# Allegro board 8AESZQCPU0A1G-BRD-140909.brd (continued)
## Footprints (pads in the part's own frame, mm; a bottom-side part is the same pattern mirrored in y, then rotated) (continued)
SODIMM_204R_R
  round 1.6 hole 1.6 unplated: (0,0)
  round 1.092 hole 1.092 unplated: (66.8,0)
  rect 0.356x2.032 smd: 1(1.75,-4.1) 2(2.05,4.1) 3(2.35,-4.1) 4(2.65,4.1) 5(2.95,-4.1) 6(3.25,4.1) 7(3.55,-4.1) 8(3.85,4.1) 9(4.15,-4.1) 10(4.45,4.1) 11(4.75,-4.1) 12(5.05,4.1) 13(5.35,-4.1) 14(5.65,4.1) 15(5.95,-4.1) 16(6.25,4.1) 17(6.55,-4.1) 18(6.85,4.1) 19(7.15,-4.1) 20(7.45,4.1) 21(7.75,-4.1) 22(8.05,4.1) 23(8.35,-4.1) 24(8.65,4.1) 25(8.95,-4.1) 26(9.25,4.1) 27(9.55,-4.1) 28(9.85,4.1) 29(10.15,-4.1) 30(10.45,4.1) 31(10.75,-4.1) 32(11.05,4.1) 33(11.35,-4.1) 34(11.65,4.1) 35(11.95,-4.1) 36(12.25,4.1) 37(12.55,-4.1) 38(12.85,4.1) 39(13.15,-4.1) 40(13.45,4.1) 41(13.75,-4.1) 42(14.05,4.1) 43(14.35,-4.1) 44(14.65,4.1) 45(14.95,-4.1) 46(15.25,4.1) 47(15.55,-4.1) 48(15.85,4.1) 49(16.15,-4.1) 50(16.45,4.1) 51(16.75,-4.1) 52(17.05,4.1) 53(17.35,-4.1) 54(17.65,4.1) 55(17.95,-4.1) 56(18.25,4.1) 57(18.55,-4.1) 58(18.85,4.1) 59(19.15,-4.1) 60(19.45,4.1) 61(19.75,-4.1) 62(20.05,4.1) 63(20.35,-4.1) 64(20.65,4.1) 65(20.95,-4.1) 66(21.25,4.1) 67(21.55,-4.1) 68(21.85,4.1) 69(22.15,-4.1) 70(22.45,4.1) 71(22.75,-4.1) 72(23.05,4.1) 73(25.75,-4.1) 74(26.05,4.1) 75(26.35,-4.1) 76(26.65,4.1) 77(26.95,-4.1) 78(27.25,4.1) 79(27.55,-4.1) 80(27.85,4.1) 81(28.15,-4.1) 82(28.45,4.1) 83(28.75,-4.1) 84(29.05,4.1) 85(29.35,-4.1) 86(29.65,4.1) 87(29.95,-4.1) 88(30.25,4.1) 89(30.55,-4.1) 90(30.85,4.1) 91(31.15,-4.1) 92(31.45,4.1) 93(31.75,-4.1) 94(32.05,4.1) 95(32.35,-4.1) 96(32.65,4.1) 97(32.95,-4.1) 98(33.25,4.1) 99(33.55,-4.1) 100(33.85,4.1) 101(34.15,-4.1) 102(34.45,4.1) 103(34.75,-4.1) 104(35.05,4.1) 105(35.35,-4.1) 106(35.65,4.1) 107(35.95,-4.1) 108(36.25,4.1) 109(36.55,-4.1) 110(36.85,4.1) 111(37.15,-4.1) 112(37.45,4.1) 113(37.75,-4.1) 114(38.05,4.1) 115(38.35,-4.1) 116(38.65,4.1) 117(38.95,-4.1) 118(39.25,4.1) 119(39.55,-4.1) 120(39.85,4.1) 121(40.15,-4.1) 122(40.45,4.1) 123(40.75,-4.1) 124(41.05,4.1) 125(41.35,-4.1) 126(41.65,4.1) 127(41.95,-4.1) 128(42.25,4.1) 129(42.55,-4.1) 130(42.85,4.1) 131(43.15,-4.1) 132(43.45,4.1) 133(43.75,-4.1) 134(44.05,4.1) 135(44.35,-4.1) 136(44.65,4.1) 137(44.95,-4.1) 138(45.25,4.1) 139(45.55,-4.1) 140(45.85,4.1) 141(46.15,-4.1) 142(46.45,4.1) 143(46.75,-4.1) 144(47.05,4.1) 145(47.35,-4.1) 146(47.65,4.1) 147(47.95,-4.1) 148(48.25,4.1) 149(48.55,-4.1) 150(48.85,4.1) 151(49.15,-4.1) 152(49.45,4.1) 153(49.75,-4.1) 154(50.05,4.1) 155(50.35,-4.1) 156(50.65,4.1) 157(50.95,-4.1) 158(51.25,4.1) 159(51.55,-4.1) 160(51.85,4.1) 161(52.15,-4.1) 162(52.45,4.1) 163(52.75,-4.1) 164(53.05,4.1) 165(53.35,-4.1) 166(53.65,4.1) 167(53.95,-4.1) 168(54.25,4.1) 169(54.55,-4.1) 170(54.85,4.1) 171(55.15,-4.1) 172(55.45,4.1) 173(55.75,-4.1) 174(56.05,4.1) 175(56.35,-4.1) 176(56.65,4.1) 177(56.95,-4.1) 178(57.25,4.1) 179(57.55,-4.1) 180(57.85,4.1) 181(58.15,-4.1) 182(58.45,4.1) 183(58.75,-4.1) 184(59.05,4.1) 185(59.35,-4.1) 186(59.65,4.1) 187(59.95,-4.1) 188(60.25,4.1) 189(60.55,-4.1) 190(60.85,4.1) 191(61.15,-4.1) 192(61.45,4.1) 193(61.75,-4.1) 194(62.05,4.1) 195(62.35,-4.1) 196(62.65,4.1) 197(62.95,-4.1) 198(63.25,4.1) 199(63.55,-4.1) 200(63.85,4.1) 201(64.15,-4.1) 202(64.45,4.1) 203(64.75,-4.1) 204(65.05,4.1)
  rect 3.556x4.699 smd: 205(0.6,-12) 206(66.2,-12)
SOP8_0P65_4P9
  rect 0.508x1.27 smd: 1(-1.102,-2.324) 4(1.102,-2.324) 5(1.102,2.324) 8(-1.102,2.324)
  rect 0.356x1.27 smd: 2(-0.325,-2.324) 3(0.325,-2.324) 6(0.325,2.324) 7(-0.325,2.324)
SOP8_0P65_6P4
  rect 0.61x1.397 smd: 1(-1.102,-3.01) 4(1.102,-3.01) 5(1.102,3.01) 8(-1.102,3.01)
  rect 0.356x1.397 smd: 2(-0.325,-3.01) 3(0.325,-3.01) 6(0.325,3.01) 7(-0.325,3.01)
SOP8_1P27_6
  rect 0.914x1.397 smd: 1(-2.032,-2.857) 4(2.032,-2.857) 5(2.032,2.857) 8(-2.032,2.857)
  rect 0.66x1.397 smd: 2(-0.635,-2.857) 3(0.635,-2.857) 6(0.635,2.857) 7(-0.635,2.857)
SOP8_1P27_7P9
  rect 0.914x1.397 smd: 1(-2.032,-3.81) 4(2.032,-3.81) 5(2.032,3.81) 8(-2.032,3.81)
  rect 0.66x1.397 smd: 2(-0.635,-3.81) 3(0.635,-3.81) 6(0.635,3.81) 7(-0.635,3.81)
SOP14_0P65_6P4_EP
  rect 0.61x1.397 smd: 1(-2.077,-3.01) 7(2.077,-3.01) 8(2.077,3.01) 14(-2.077,3.01)
  rect 0.356x1.397 smd: 2(-1.3,-3.01) 3(-0.65,-3.01) 4(0,-3.01) 5(0.65,-3.01) 6(1.3,-3.01) 9(1.3,3.01) 10(0.65,3.01) 11(0,3.01) 12(-0.65,3.01) 13(-1.3,3.01)
  rect 2.311x2.464 smd: 15(0,0)
SOP14_0P65_6P4_EP_JNPR_1
  rect 0.61x1.397 smd: 1(-2.077,-3.01) 7(2.077,-3.01) 8(2.077,3.01) 14(-2.077,3.01)
  rect 0.356x1.397 smd: 2(-1.3,-3.01) 3(-0.65,-3.01) 4(0,-3.01) 5(0.65,-3.01) 6(1.3,-3.01) 9(1.3,3.01) 10(0.65,3.01) 11(0,3.01) 12(-0.65,3.01) 13(-1.3,3.01)
  rect 2.311x2.464 smd: 15(0,0)
SOT_23
  rect 0.889x1.219 smd: 1(-0.95,-1.219) 2(0.95,-1.219) 3(0,1.219)
SOT_25
  rect 0.61x1.27 smd: 1(-0.965,-1.27) 2(0,-1.27) 3(0.965,-1.27) 4(0.965,1.27) 5(-0.965,1.27)
SOT_363
  rect 0.508x0.889 smd: 1(-0.724,-1.016) 3(0.724,-1.016) 4(0.724,1.016) 6(-0.724,1.016)
  rect 0.356x0.889 smd: 2(0,-1.016) 5(0,1.016)
T30
  round 0.762 smd: 1(0,0)
TO_252AA
  rect 1.27x2.794 smd: 1(-2.286,-4.572) 3(2.286,-4.572)
  rect 5.588x7.62 smd: 2(0,1.778)
unnamed#2
  round 3.2 hole 3.2 unplated: (0,0)
XTAL2_TXC_9H
  rect 1.524x1.778 smd: 1(-1.778,0) 2(1.778,0)
XTAL4_FL2000006
  rect 1.524x1.346 smd: 1(-1.219,-0.978) 2(1.219,-0.978) 3(1.219,0.978) 4(-1.219,0.978)

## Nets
3.3V_FB: C389.1 R77.2 R268.2 U17.1(VFB)
5V_EN: R336.1 U29.7(EN)
5V_FB: C484.1 R339.1 R344.1 U29.2(VFB)
5V_GOOD: R127.2 U29.6(PG)
5V_SS: C483.1 U29.4(SS) U41.3(DRAIN)
12V_HOLD: C135.1 D11.2(CATHODE) R114.1 R336.2 R338.1 U29.13(VIN) U29.14(VCC)
AGND_V1P0: C158.2 N56.2 N57.1 R128.1 U31.4(AGND) U31.17(GND)
GND: A1.3 A1.4 A1.6 A1.7 A1.8 C1.2 C2.2 C3.2 C4.2 C5.2 C7.2 C8.2 C9.2 C10.2 C11.2 C12.2 C13.2 C14.2 C15.2 C17.2 C18.2 C19.2 C21.2 C22.2 C24.2 C25.2 C26.2 C27.2 C28.2 C30.2 C39.2 C42.2 C43.2 C44.2 C45.2 C46.2 C47.2 C48.2 C49.2 C50.2 C51.2 C52.2 C53.2 C54.2 C55.2 C56.2 C57.2 C58.2 C59.2 C60.2 C61.2 C62.2 C63.1 C64.2 C65.2 C66.1 C68.2 C69.2 C70.2 C71.2 C72.2 C76.2 C77.2 C78.2 C80.2 C81.2 C82.2 C83.2 C84.2 C86.1 C88.2 C89.2 C90.2 C91.2 C92.2 C93.2 C94.2 C95.2 C96.1 C97.2 C98.2 C99.2 C100.2 C101.2 C102.2 C105.2 C108.1 C114.2 C115.2 C116.2 C117.2 C118.2 C119.2 C120.2 C121.2 C122.2 C123.2 C124.1 C125.2 C126.1 C127.2 C128.2 C129.2 C130.1 C131.2 C132.2 C133.2 C134.2 C135.2 C136.1 C137.2 C138.2 C139.2 C140.2 C141.2 C142.2 C143.2 C144.2 C145.2 C146.2 C147.2 C148.1 C149.2 C151.2 C152.2 C153.1 C154.1 C155.1 C156.2 C157.2 C159.2 C160.2 C161.2 C162.2 C163.2 C165.2 C166.2 C167.2 C168.2 C169.2 C170.2 C171.2 C172.2 C173.2 C174.2 C175.2 C176.2 C177.2 C178.2 C179.2 C180.2 C181.2 C182.2 C183.2 C185.2 C186.2 C187.2 C188.2 C189.2 C190.2 C191.2 C192.2 C193.2 C194.2 C195.2 C196.2 C197.2 C198.2 C199.2 C200.2 C201.2 C202.2 C203.2 C204.2 C205.2 C206.2 C207.2 C208.2 C209.2 C210.2 C211.2 C212.2 C213.2 C214.2 C215.2 C216.2 C217.2 C218.2 C219.2 C221.2 C222.2 C223.2 C224.2 C225.2 C226.2 C227.2 C228.2 C229.2 C230.2 C231.2 C232.2 C233.2 C234.2 C236.2 C237.2 C238.2 C241.2 C244.2 C245.2 C247.2 C248.2 C249.2 C250.2 C251.2 C252.2 C255.2 C256.2 C257.2 C258.2 C259.2 C260.2 C261.2 C262.2 C263.2 C264.2 C265.2 C266.2 C267.2 C268.2 C269.2 C270.2 C271.2 C272.2 C273.2 C274.2 C275.2 C276.2 C277.2 C278.2 C279.2 C280.2 C281.2 C282.2 C283.2 C284.2 C285.2 C286.2 C287.2 C288.2 C289.2 C290.2 C291.2 C293.2 C294.2 C295.2 C296.2 C299.2 C300.2 C301.2 C302.2 C303.2 C304.2 C305.2 C306.2 C307.2 C308.2 C309.2 C310.2 C311.2 C312.2 C315.2 C316.2 C317.2 C318.2 C319.2 C320.2 C321.2 C322.2 C323.2 C324.2 C325.2 C326.2 C327.1 C328.2 C329.2 C330.2 C331.2 C332.2 C333.2 C334.2 C335.2 C336.2 C337.2 C339.2 C340.2 C341.2 C342.2 C343.2 C344.2 C345.2 C346.2 C347.2 C349.2 C350.2 C351.2 C352.2 C353.2 C354.2 C355.2 C356.2 C357.2 C358.2 C359.2 C360.2 C361.2 C362.2 C363.2 C365.2 C366.2 C367.2 C368.2 C369.2 C370.2 C371.2 C372.2 C373.2 C374.2 C375.2 C376.2 C377.2 C378.2 C379.2 C380.2 C381.2 C382.2 C383.2 C384.2 C385.2 C386.2 C387.2 C388.2 C390.2 C391.2 C392.2 C393.2 C394.2 C396.2 C397.2 C398.2 C399.2 C400.2 C401.2 C402.2 C403.2 C404.2 C405.2 C406.2 C407.2 C408.2 C409.2 C410.2 C411.2 C412.2 C413.2 C415.2 C416.2 C417.2 C418.2 C420.2 C422.2 C423.2 C424.2 C425.2 C426.2 C427.2 C432.2 C434.2 C435.2 C436.2 C437.2 C438.2 C439.2 C440.2 C441.2 C442.2 C443.2 C445.2 C446.2 C449.2 C451.2 C453.2 C454.2 C455.2 C456.1 C457.2 C458.2 C459.2 C460.2 C461.2 C462.1 C463.2 C464.2 C465.2 C466.2 C467.2 C468.2 C469.2 C470.2 C471.2 C472.2 C473.2 C474.2 C475.2 C476.2 C477.2 C479.2 C480.2 C481.2 C482.2 C483.2 C485.2 C489.1 C490.1 C491.1 C492.1 C493.1 C494.1 C495.1 C496.1 C498.2 C499.2 C500.2 C501.2 J1.3 J2.3 J3.3 J4.3 J5.3 JP2.4 JP3.2 JP3.10 JP4.1 JP4.2 JP4.3 JP4.4 JP5.4 N3.2 N13.2 N18.2 N29.2 N31.1 N32.1 N36.1 N39.2 N41.2 N45.2 N51.1 N56.1 N58.2 P1.2(GND24) P1.3(GND1) P1.8(GND25) P1.9(GND2) P1.11(DM0) P1.14(GND26) P1.17(GND3) P1.20(GND27) P1.23(GND4) P1.26(GND28) P1.28(DM1) P1.29(GND5) P1.32(GND29) P1.35(GND6) P1.38(GND30) P1.41(GND7) P1.44(DM2) P1.46(GND31) P1.47(GND8) P1.52(GND32) P1.53(GND9) P1.58(GND33) P1.59(DM3) P1.61(GND10) P1.64(GND34) P1.67(GND11) P1.70(GND35) P1.73(GND12) P1.76(DM8) P1.78(GND36) P1.79(GND13) P1.137(GND14) P1.138(GND37) P1.140(DM4) P1.143(GND15) P1.146(GND38) P1.149(GND16) P1.152(GND39) P1.155(GND17) P1.157(DM5) P1.158(GND40) P1.163(GND18) P1.164(GND41) P1.169(GND19) P1.170(GND42) P1.172(DM6) P1.175(GND20) P1.178(GND43) P1.181(GND21) P1.184(GND44#184) P1.187(GND22) P1.189(DM7) P1.190(GND44#190) P1.195(GND23) P1.196(GND45) P1.205(GATE1) P1.206(GATE2) P2.1(GND0) P2.2(GND1) P2.7(GND2) P2.8(GND3) P2.13(GND4) P2.14(GND5) P2.19(GND6) P2.20(GND7) P2.25(GND8) P2.26(GND9) P2.31(GND10) P2.32(GND11) P2.37(GND12) P2.38(GND13) P2.49(GND14) P2.50(GND15) P2.59(GND16) P2.60(GND17) P3.1 P3.4 P3.7 P3.11 P3.12 P3.13 P3.17 P3.19 P3.23 P3.24 P4.2(GND24) P4.3(GND1) P4.8(GND25) P4.9(GND2) P4.11(DM0) P4.14(GND26) P4.17(GND3) P4.20(GND27) P4.23(GND4) P4.26(GND28) P4.28(DM1) P4.29(GND5) P4.32(GND29) P4.35(GND6) P4.38(GND30) P4.41(GND7) P4.44(DM2) P4.46(GND31) P4.47(GND8) P4.52(GND32) P4.53(GND9) P4.58(GND33) P4.59(DM3) P4.61(GND10) P4.64(GND34) P4.67(GND11) P4.70(GND35) P4.73(GND12) P4.76(DM8) P4.78(GND36) P4.79(GND13) P4.137(GND14) P4.138(GND37) P4.140(DM4) P4.143(GND15) P4.146(GND38) P4.149(GND16) P4.152(GND39) P4.155(GND17) P4.157(DM5) P4.158(GND40) P4.163(GND18) P4.164(GND41) P4.169(GND19) P4.170(GND42) P4.172(DM6) P4.175(GND20) P4.178(GND43) P4.181(GND21) P4.184(GND44#184) P4.187(GND22) P4.189(DM7) P4.190(GND44#190) P4.195(GND23) P4.196(GND45) P4.205(GATE1) P4.206(GATE2) R1.2 R3.2 R10.2 R11.1 R14.1 R25.1 R35.2 R39.2 R55.1 R64.2 R71.2 R76.2 R77.1 R85.1 R86.1 R99.2 R106.2 R116.2 R119.2 R121.2 R123.1 R124.2 R126.1 R129.2 R130.2 R135.2 R137.2 R144.1 R149.2 R155.1 R157.1 R164.2 R165.2 R166.2 R167.2 R173.1 R177.2 R178.2 R179.2 R181.2 R183.2 R188.2 R189.2 R192.2 R197.2 R211.2 R212.2 R213.2 R221.2 R223.2 R224.2 R226.2 R227.2 R228.2 R231.2 R234.2 R237.1 R238.2 R242.1 R245.1 R255.1 R261.2 R262.2 R263.2 R264.1 R265.2 R271.1 R274.2 R275.2 R277.2 R278.1 R279.1 R280.1 R286.2 R294.1 R295.1 R299.2 R303.2 R304.1 R305.1 R306.2 R317.2 R318.2 R321.2 R322.2 R325.1 R332.1 R333.2 R341.2 R344.2 R345.2 R346.1 S1.A1(PRSNT#) S1.A4(GND#A4) S1.A12(GND#A12) S1.A15(GND#A15) S1.A16(GND#A16) S1.A19(GND#A19) S1.A20(GND#A20) S1.A23(GND#A23) S1.A24(GND#A24) S1.A27(GND#A27) S1.A28(GND#A28) S1.A31(GND#A31) S1.A32(GND#A32) S1.A35(GND#A35) S1.A36(GND#A36) S1.A39(GND#A39) S1.A40(GND#A40) S1.A43(GND#A43) S1.A44(GND#A44) S1.A47(GND#A47) S1.A48(GND#A48) S1.A51(GND#A51) S1.A52(GND#A52) S1.A55(GND#A55) S1.A56(GND#A56) S1.A59(GND#A59) S1.A60(GND#A60) S1.A63(GND#A63) S1.A64(GND#A64) S1.A67(GND#A67) S1.A68(GND#A68) S1.A71(GND#A71) S1.A72(GND#A72) S1.A75(GND#A75) S1.A76(GND#A76) S1.A79(GND#A79) S1.A80(GND#A80) S1.B4(GND#B4) S1.B7(GND#B7) S1.B13(GND#B13) S1.B14(GND#B14) S1.B17(GND#B17) S1.B18(GND#B18) S1.B21(GND#B21) S1.B22(GND#B22) S1.B25(GND#B25) S1.B26(GND#B26) S1.B29(GND#B29) S1.B30(GND#B30) S1.B33(GND#B33) S1.B34(GND#B34) S1.B37(GND#B37) S1.B38(GND#B38) S1.B41(GND#B41) S1.B42(GND#B42) S1.B45(GND#B45) S1.B46(GND#B46) S1.B49(GND#B49) S1.B50(GND#B50) S1.B53(GND#B53) S1.B54(GND#B54) S1.B57(GND#B57) S1.B58(GND#B58) S1.B61(GND#B61) S1.B62(GND#B62) S1.B65(GND#B65) S1.B66(GND#B66) S1.B69(GND#B69) S1.B70(GND#B70) S1.B73(GND#B73) S1.B74(GND#B74) S1.B77(GND#B77) S1.B78(GND#B78) S1.B81(GND#B81) S1.B82(GND#B82) U1.3(GND) U2.1(CSIN_N) U2.2(CSIN_P) U2.4(PGND1) U2.12(PGND2) U2.13(PGND3) U2.21(LGND) U2.22(REFIN) U3.26(VRTN_L2) U3.27(VSEN_L2) U3.41(GND) U5.4(GND) U6.2(GND) U7.A1(GNDIO#A1) U7.A16(GNDIO#A16) U7.B2(GNDIO#B2) U7.B15(GNDIO#B15) U7.F7(IO_2_F7/DIFFIO_T8P) U7.G5(GNDIO#G5) U7.G6(IO_1_G6) U7.G7(GNDIO#G7) U7.G8(GNDIO#G8) U7.G9(GNDIO#G9) U7.G10(GNDIO#G10) U7.H7(GNDINT#H7) U7.H9(GNDINT#H9) U7.J8(GNDINT#J8) U7.J10(GNDINT#J10) U7.K7(GNDIO#K7) U7.K8(GNDIO#K8) U7.K9(GNDIO#K9) U7.K10(GNDIO#K10) U7.K11(IO_3_K11) U7.L10(IO_4_L10) U7.R2(GNDIO#R2) U7.R15(GNDIO#R15) U7.T1(GNDIO#T1) U7.T6(IO_4_T6/DIFFIO_B9P) U7.T16(GNDIO#T16) U8.4(GND) U9.4(GND) U10.2(GND) U11.3(GND) U12.1(CSIN_N) U12.2(CSIN_P) U12.4(PGND1) U12.12(PGND2) U12.13(PGND3) U12.21(LGND) U12.22(REFIN) U13.3(GND) U14.A5(VSS#A5) U14.A9(VSS#A9) U14.A12(VSS#A12) U14.A15(VSS#A15) U14.A18(VSS#A18) U14.A24(VSS#A24) U14.A30(VSS#A30) U14.A33(VSS#A33) U14.A45(VSS#A45) U14.A48(VSS#A48) U14.A51(VSS#A51) U14.A57(VSS#A57) U14.A59(VSS#A59) U14.A61(VSS#A61) U14.A62(VSS#A62) U14.A64(VSS#A64) U14.A66(VSS#A66) U14.AA3(VSS#AA3) U14.AA5(VSS#AA5) U14.AA23(VSS#AA23) U14.AA25(VSS#AA25) U14.AA26(VSS#AA26) U14.AA28(VSS#AA28) U14.AA29(VSS#AA29) U14.AA31(VSS#AA31) U14.AA36(VSS#AA36) U14.AA42(VSS#AA42) U14.AA44(VSS#AA44) U14.AA62(VSS#AA62) U14.AA64(VSS#AA64) U14.AA66(VSS#AA66) U14.AB1(VSS#AB1) U14.AB5(VSS#AB5) U14.AB20(VSS#AB20) U14.AC12(VSS#AC12) U14.AC18(VSS#AC18) U14.AC20(VSS#AC20) U14.AC21(VSS#AC21) U14.AC23(VSS#AC23) U14.AC28(VSS#AC28) U14.AC29(VSS#AC29) U14.AC31(VSS#AC31) U14.AC32(VSS#AC32) U14.AC34(VSS#AC34) U14.AC36(VSS#AC36) U14.AC46(VSS#AC46) U14.AC50(VSS#AC50) U14.AC55(VSS#AC55) U14.AC59(VSS#AC59) U14.AD2(VSS#AD2) U14.AD4(VSS#AD4) U14.AD5(VSS#AD5) U14.AD9(VSS#AD9) U14.AD14(VSS#AD14) U14.AD17(VSS#AD17) U14.AD18(VSS#AD18) U14.AD20(VSS#AD20) U14.AD34(VSS#AD34) U14.AD41(VSS#AD41) U14.AD46(VSS#AD46) U14.AD47(VSS#AD47) U14.AD52(VSS#AD52) U14.AD56(VSS#AD56) U14.AD62(VSS#AD62) U14.AE47(VSS#AE47) U14.AE64(VSS#AE64) U14.AF28(VSS#AF28) U14.AF44(VSS#AF44) U14.AF62(VSS#AF62) U14.AG5(VSS#AG5) U14.AG10(VSS#AG10) U14.AG16(VSS#AG16) U14.AG23(VSS#AG23) U14.AG25(VSS#AG25) U14.AG26(VSS#AG26) U14.AG28(VSS#AG28) U14.AG34(VSS#AG34) U14.AG41(VSS#AG41) U14.AG44(VSS#AG44) U14.AG48(VSS#AG48) U14.AG53(VSS#AG53) U14.AG57(VSS#AG57) U14.AG63(VSS#AG63) U14.AG64(VSS#AG64) U14.AG66(VSS#AG66) U14.AH11(VSS#AH11) U14.AH17(VSS#AH17) U14.AH53(VSS#AH53) U14.AH57(VSS#AH57) U14.AH62(VSS#AH62) U14.AJ28(VSS#AJ28) U14.AJ32(VSS#AJ32) U14.AJ44(VSS#AJ44) U14.AJ46(VSS#AJ46) U14.AJ47(VSS#AJ47) U14.AK3(VSS#AK3) U14.AK5(VSS#AK5) U14.AK62(VSS#AK62) U14.AK64(VSS#AK64) U14.AK66(VSS#AK66) U14.AL1(VSS#AL1) U14.AL5(VSS#AL5) U14.AL9(VSS#AL9) U14.AL14(VSS#AL14) U14.AL17(VSS#AL17) U14.AL18(VSS#AL18) U14.AL20(VSS#AL20) U14.AL29(VSS#AL29) U14.AL38(VSS#AL38) U14.AL42(VSS#AL42) U14.AL44(VSS#AL44) U14.AL50(VSS#AL50) U14.AL55(VSS#AL55) U14.AL59(VSS#AL59) U14.AM12(VSS#AM12) U14.AM18(VSS#AM18) U14.AM20(VSS#AM20) U14.AM21(VSS#AM21) U14.AM23(VSS#AM23) U14.AM44(VSS#AM44) U14.AM46(VSS#AM46) U14.AM50(VSS#AM50) U14.AM55(VSS#AM55) U14.AM59(VSS#AM59) U14.AN5(VSS#AN5) U14.AN47(VSS#AN47) U14.AN66(VSS#AN66) U14.AP5(VSS#AP5) U14.AP23(VSS#AP23) U14.AP25(VSS#AP25) U14.AP26(VSS#AP26) U14.AP28(VSS#AP28) U14.AP29(VSS#AP29) U14.AP31(VSS#AP31) U14.AP32(VSS#AP32) U14.AP34(VSS#AP34) U14.AP36(VSS#AP36) U14.AP38(VSS#AP38) U14.AP39(VSS#AP39) U14.AP41(VSS#AP41) U14.AP42(VSS#AP42) U14.AP44(VSS#AP44) U14.AP46(VSS#AP46) U14.AP64(VSS#AP64) U14.AR8(VSS#AR8) U14.AR13(VSS#AR13) U14.AR17(VSS#AR17) U14.AR19(VSS#AR19) U14.AR50(VSS#AR50) U14.AR56(VSS#AR56) U14.AR60(VSS#AR60) U14.AR62(VSS#AR62) U14.AT5(VSS#AT5) U14.AT11(VSS#AT11) U14.AT16(VSS#AT16) U14.AT17(VSS#AT17) U14.AT19(VSS#AT19) U14.AT44(VSS#AT44) U14.AT53(VSS#AT53) U14.AT57(VSS#AT57) U14.AT64(VSS#AT64) U14.AT66(VSS#AT66) U14.AU4(VSS#AU4) U14.AU44(VSSA_USB#AU44) U14.AU62(VSS#AU62) U14.AV2(VSS#AV2) U14.AV4(VSS#AV4) U14.AV5(VSS#AV5) U14.AW5(VSS#AW5) U14.AW9(VSS#AW9) U14.AW14(VSS#AW14) U14.AW19(VSS#AW19) U14.AW23(VSS#AW23) U14.AW25(VSS#AW25) U14.AW26(VSS#AW26) U14.AW28(VSS#AW28) U14.AW30(VSS#AW30) U14.AW31(VSS#AW31) U14.AW32(VSS#AW32) U14.AW34(VSS#AW34) U14.AW44(VSSA_USB#AW44) U14.AW46(VSS#AW46) U14.AW47(VSS#AW47) U14.AW49(VSS#AW49) U14.AW50(VSS#AW50) U14.AW52(VSS#AW52) U14.AW55(VSS#AW55) U14.AW59(VSS#AW59) U14.AY5(VSS#AY5) U14.AY12(VSS#AY12) U14.AY38(VSS#AY38) U14.AY45(VSS#AY45) U14.AY52(VSS#AY52) U14.AY55(VSS#AY55) U14.AY62(VSS#AY62) U14.B10(VSS#B10) U14.B26(VSS#B26) U14.B41(VSS#B41) U14.B55(VSS#B55) U14.BA17(VSS#BA17) U14.BA29(VSS#BA29) U14.BA34(VSS#BA34) U14.BA42(VSS#BA42) U14.BA49(VSS#BA49) U14.BB5(VSS#BB5) U14.BB17(VSS#BB17) U14.BB34(VSS#BB34) U14.BB53(VSS#BB53) U14.BB54(VSS#BB54) U14.BB56(VSS#BB56) U14.BB57(VSS#BB57) U14.BB62(VSS#BB62) U14.BB65(VSS#BB65) U14.BB66(VSS#BB66) U14.BC5(VSS#BC5) U14.BC30(VSS#BC30) U14.BC37(VSS#BC37) U14.BC46(VSS#BC46) U14.BD32(VSS#BD32) U14.BD34(VSS#BD34) U14.BD38(VSS#BD38) U14.BD41(VSS#BD41) U14.BD45(VSS#BD45) U14.BD50(VSS#BD50) U14.BD53(VSS#BD53) U14.BD59(VSS#BD59) U14.BD60(VSS#BD60) U14.BD62(VSS#BD62) U14.BD63(VSS#BD63) U14.BD65(VSS#BD65) U14.BE5(VSS#BE5) U14.BE32(VSS#BE32) U14.BE42(VSS#BE42) U14.BE49(VSS#BE49) U14.BE57(VSS#BE57) U14.BE66(VSS#BE66) U14.BF1(VSS#BF1) U14.BF3(VSS#BF3) U14.BF4(VSS#BF4) U14.BF29(VSS#BF29) U14.BF62(VSS#BF62) U14.BG1(VSS#BG1) U14.BG32(VSS#BG32) U14.BG37(VSS#BG37) U14.BG46(VSS#BG46) U14.BG54(VSS#BG54) U14.BG63(VSS#BG63) U14.BG66(VSS#BG66) U14.BH32(VSS#BH32) U14.BH34(VSS#BH34) U14.BH41(VSS#BH41) U14.BH50(VSS#BH50) U14.BH60(VSS#BH60) U14.BH62(VSS#BH62) U14.BJ1(VSS#BJ1) U14.BJ66(VSS#BJ66) U14.BK1(VSS#BK1) U14.BK8(VSS#BK8) U14.BK10(VSS#BK10) U14.BK15(VSS#BK15) U14.BK17(VSS#BK17) U14.BK18(VSS#BK18) U14.BK19(VSS#BK19) U14.BK21(VSS#BK21) U14.BK22(VSS#BK22) U14.BK24(VSS#BK24) U14.BK26(VSS#BK26) U14.BK27(VSS#BK27) U14.BK28(VSS#BK28) U14.BK30(VSS#BK30) U14.BK31(VSS#BK31) U14.BK36(VSS#BK36) U14.BK37(VSS#BK37) U14.BK39(VSS#BK39) U14.BK42(VSS#BK42) U14.BK44(VSS#BK44) U14.BK45(VSS#BK45) U14.BK46(VSS#BK46) U14.BK48(VSS#BK48) U14.BK49(VSS#BK49) U14.BK51(VSS#BK51) U14.BK53(VSS#BK53) U14.BK56(VSS#BK56) U14.BK57(VSS#BK57) U14.BK58(VSS#BK58) U14.BK64(VSS#BK64) U14.BK66(VSS#BK66) U14.BL14(VSS#BL14) U14.BL19(VSS#BL19) U14.BL25(VSS#BL25) U14.BL30(VSS#BL30) U14.BL34(VSS#BL34) U14.BL37(VSS#BL37) U14.BL43(VSS#BL43) U14.BM1(VSS#BM1) U14.BM3(VSS#BM3) U14.BM5(VSS#BM5) U14.BM22(VSS#BM22) U14.BM45(VSS#BM45) U14.BM61(VSS#BM61) U14.BM62(VSS#BM62) U14.BM64(VSS#BM64) U14.BM66(VSS#BM66) U14.BN14(VSS#BN14) U14.BN30(VSS#BN30) U14.BN37(VSS#BN37) U14.BP1(VSS#BP1) U14.BP3(VSS#BP3) U14.BP5(VSS#BP5) U14.BP10(VSS#BP10) U14.BP13(VSS#BP13) U14.BP22(VSS#BP22) U14.BP31(VSS#BP31) U14.BP37(VSS#BP37) U14.BP40(VSS#BP40) U14.BP46(VSS#BP46) U14.BP52(VSS#BP52) U14.BP55(VSS#BP55) U14.BP58(VSS#BP58) U14.BP59(VSS#BP59) U14.BP61(VSS#BP61) U14.BP62(VSS#BP62) U14.BP64(VSS#BP64) U14.BP66(VSS#BP66) U14.C3(VSS#C3) U14.C6(VSS#C6) U14.C18(VSS#C18) U14.C33(VSS#C33) U14.C45(VSS#C45) U14.C49(VSS#C49) U14.C51(VSS#C51) U14.C58(VSS#C58) U14.C64(VSS#C64) U14.C66(VSS#C66) U14.D6(VSS#D6) U14.D10(VSS#D10) U14.D26(VSS#D26) U14.D33(VSS#D33) U14.D41(VSS#D41) U14.D42(VSS#D42) U14.D51(VSS#D51) U14.D55(VSS#D55) U14.D59(VSS#D59) U14.E1(VSS#E1) U14.E3(VSS#E3) U14.E10(VSS#E10) U14.E13(VSS#E13) U14.E14(VSS#E14) U14.E16(VSS#E16) U14.E18(VSS#E18) U14.E19(VSS#E19) U14.E21(VSS#E21) U14.E22(VSS#E22) U14.E23(VSS#E23) U14.E25(VSS#E25) U14.E27(VSS#E27) U14.E28(VSS#E28) U14.E30(VSS#E30) U14.E31(VSS#E31) U14.E34(VSS#E34) U14.E36(VSS#E36) U14.E37(VSS#E37) U14.E39(VSS#E39) U14.E40(VSS#E40) U14.E41(VSS#E41) U14.E43(VSS#E43) U14.E45(VSS#E45) U14.E46(VSS#E46) U14.E48(VSS#E48) U14.E49(VSS#E49) U14.E50(VSS#E50) U14.E52(VSS#E52) U14.E54(VSS#E54) U14.E55(VSS#E55) U14.E59(VSS#E59) U14.E61(VSS#E61) U14.E64(VSS#E64) U14.E66(VSS#E66) U14.F1(VSS#F1) U14.F4(VSS#F4) U14.F5(VSS#F5) U14.F63(VSS#F63) U14.F66(VSS#F66) U14.G32(VSS#G32) U14.G34(VSS#G34) U14.G41(VSS#G41) U14.G48(VSS#G48) U14.G56(VSS#G56) U14.G59(VSS#G59) U14.H1(VSS#H1) U14.H34(VSS#H34) U14.H37(VSS#H37) U14.H38(VSS#H38) U14.H41(VSS#H41) U14.H44(VSS#H44) U14.H46(VSS#H46) U14.H52(VSS#H52) U14.H54(VSS#H54) U14.H56(VSS#H56) U14.H58(VSS#H58) U14.H59(VSS#H59) U14.H66(VSS#H66) U14.J29(VSS#J29) U14.J63(VSS#J63) U14.J64(VSS#J64) U14.J66(VSS#J66) U14.K1(VSS#K1) U14.K32(VSS#K32) U14.K34(VSS#K34) U14.K42(VSS#K42) U14.K50(VSS#K50) U14.K62(VSS#K62) U14.L30(VSS#L30) U14.L34(VSS#L34) U14.L48(VSS#L48) U14.L50(VSS#L50) U14.L60(VSS#L60) U14.M5(VSS#M5) U14.M37(VSS#M37) U14.M38(VSS#M38) U14.M44(VSS#M44) U14.M46(VSS#M46) U14.M52(VSS#M52) U14.M54(VSS#M54) U14.M56(VSS#M56) U14.M57(VSS#M57) U14.M59(VSS#M59) U14.M60(VSS#M60) U14.M66(VSS#M66) U14.N1(VSS#N1) U14.N5(VSS#N5) U14.N10(VSS#N10) U14.N34(VSS#N34) U14.N48(VSS#N48) U14.N50(VSS#N50) U14.N62(VSS#N62) U14.N63(VSS#N63) U14.N65(VSS#N65) U14.P29(VSS#P29) U14.P32(VSS#P32) U14.P34(VSS#P34) U14.P37(VSS#P37) U14.P44(VSS#P44) U14.R2(VSS#R2) U14.R4(VSS#R4) U14.R5(VSS#R5) U14.R12(VSS#R12) U14.R30(VSS#R30) U14.R38(VSS#R38) U14.R52(VSS#R52) U14.R56(VSS#R56) U14.R62(VSS#R62) U14.T5(VSS#T5) U14.T18(VSS#T18) U14.T20(VSS#T20) U14.T21(VSS#T21) U14.T23(VSS#T23) U14.T28(VSS#T28) U14.T29(VSS#T29) U14.T31(VSS#T31) U14.T34(VSS#T34) U14.T36(VSS#T36) U14.T41(VSS#T41) U14.T42(VSS#T42) U14.T47(VSS#T47) U14.T52(VSS#T52) U14.T56(VSS#T56) U14.T62(VSS#T62) U14.U9(VSS#U9) U14.U14(VSS#U14) U14.U62(VSS#U62) U14.U63(VSS#U63) U14.U65(VSS#U65) U14.V5(VSS#V5) U14.V32(VSS#V32) U14.V36(VSS#V36) U14.V42(VSS#V42) U14.V44(VSS#V44) U14.W4(VSS#W4) U14.W11(VSS#W11) U14.W16(VSS#W16) U14.W17(VSS#W17) U14.W19(VSS#W19) U14.W32(VSS#W32) U14.W36(VSS#W36) U14.W39(VSS#W39) U14.W42(VSS#W42) U14.W48(VSS#W48) U14.W53(VSS#W53) U14.W57(VSS#W57) U14.W62(VSS#W62) U14.Y5(VSS#Y5) U14.Y8(VSS#Y8) U14.Y13(VSS#Y13) U14.Y17(VSS#Y17) U14.Y19(VSS#Y19) U14.Y48(VSS#Y48) U14.Y51(VSS#Y51) U14.Y56(VSS#Y56) U14.Y60(VSS#Y60) U15.4(GND) U16.4(GND) U17.23(PWPD) U19.4(S) U19.8(S1) U20.7(GND) U20.11(GND_PAD) U21.4(GND) U21.41(EPAD) U23.41(GND) U24.4(VSS) U25.5(GND) U25.8(PGND1) U25.9(PGND2) U25.15(PWPD) U26.6(GND1) U26.11(GND2) U27.11(GNDPCI) U27.12(GND25) U27.17(GND48) U27.24(GNDSATA) U27.25(GNDSRC1) U27.34(GNDSRC2) U27.44(GNDDIF) U27.48(GNDREF) U27.49(TPAD) U28.6(GND1) U28.11(GND2) U29.5(GND) U29.8(PGND1) U29.9(PGND2) U29.15(PWPD) U30.6(GND1) U30.11(GND2) U31.11(PGND) U32.2(GND) U33.2(VSS) U34.2(GND) U35.2(VSS) U36.3(GND) U37.3(GND) U38.4(PGND) U38.8(GND) U38.11(GND_PAD) U39.2(SOURCE) U41.2(SOURCE) U42.2(SOURCE) X1.2(GND) X3.2(G2) X3.4(G4)
V1P0: C78.1 C159.1 C160.1 C161.1 C239.2 C257.1 C260.1 C284.1 C286.1 C287.1 C288.1 C290.1 C294.1 C303.1 C304.1 C305.1 C306.1 C316.1 C318.1 C330.1 C342.1 C343.1 C349.1 C350.1 C352.1 C354.1 C357.1 C359.1 C363.1 C373.1 C375.1 C376.1 C377.1 C381.1 C393.1 C397.1 C410.1 C411.1 C412.1 C498.1 C499.1 C500.1 C501.1 L3.1 L12.2 L14.2 L16.2 L17.1 N6.2 N59.2 N60.1 P2.43(VCC_OBS_AB) P2.44(VCC_OBS_CD) R23.1 R45.2 R50.2 R51.1 R66.2 R69.2 R75.2 R174.1 R184.2 R185.2 R198.2 R202.1 R220.2 R225.1 R236.2 U6.6(VREFB) U10.6(VREFB) U14.AA21(VCCADDR_1_1P0#AA21) U14.AA38(VCCDIGXXXSUS_1P03#AA38) U14.AA39(VCCDIGXXXSUS_1P03#AA39) U14.AA41(VCCDIGXXXSUS_1P03#AA41) U14.AC38(VCCDIGXXXSUS_1P03#AC38) U14.AC39(VCCDIGXXXSUS_1P03#AC39) U14.AC41(VCCDIGXXXSUS_1P03#AC41) U14.AC42(VCCFHVSOCSI0_1P03#AC42) U14.AC44(VCCFHVSOCSI0_1P03#AC44) U14.AD28(VCCFHVCPUSI0_MOD0_1P03) U14.AD29(VCCFHVCPUSI0_MOD2_1P03) U14.AD38(VCCDIGXXXSI0_1P03#AD38) U14.AF38(VCCDIGXXXSI0_1P03#AF38) U14.AG38(VCCDIGXXXSI0_1P03#AG38) U14.AJ29(VCCFHVCPUSI0_MOD3_1P03) U14.AJ38(VCCDIGXXXSI0_1P03#AJ38) U14.AL28(VCCFHVCPUSI0_MOD1_1P03) U14.AT21(VCCADDR_0_1P0#AT21) U14.AT23(VCCADDR_0_1P0#AT23) U14.AT25(VCCADDR_0_1P0#AT25) U14.AT26(VCCADDR_0_1P0#AT26) U14.AT28(VCCADDR_0_1P0#AT28) U14.AT36(VCCA_PCIE_1P0#AT36) U14.AT38(VCCA_PCIE_1P0#AT38) U14.AT39(VCCAREF_PCIE_HVGEN) U14.AT41(VCCDUSBSUS_1P0) U14.AT42(VCCAUSB_1P0) U14.AU21(VCCADLLDDR_0_1P0#AU21) U14.AU23(VCCADLLDDR_0_1P0#AU23) U14.AU25(VCCADLLDDR_0_1P0#AU25) U14.AU26(VCCADLLDDR_0_1P0#AU26) U14.AU28(VCCADLLDDR_0_1P0#AU28) U14.AU36(VCCA_PCIE_1P0#AU36) U14.AU38(VCCA_PCIE_1P0#AU38) U14.AU39(VCCA_PCIE_1P0#AU39) U14.AU41(VCCDUSB_1P0#AU41) U14.AW36(VCCA_PCIE_1P0#AW36) U14.AW41(VCCDUSB_1P0#AW41) U14.AY37(VCCAPLL_PCIE_1P0#AY37) U14.BA37(VCCAPLL_PCIE_1P0#BA37) U14.K41(VCCA_SATA_1P0#K41) U14.L41(VCCA_SATA_1P0#L41) U14.L42(VCCA_SATA3_1P0#L42) U14.N41(VCCA_SATA_1P0#N41) U14.N42(VCCA_SATA3_1P0#N42) U14.P41(VCCA_SATA_1P0#P41) U14.P42(VCCA_SATA3_1P0#P42) U14.R44(VCCAPLL_SATA3_1P0#R44) U14.R46(VCCAPLL_SATA_1P0#R46) U14.T37(VCCA_GBE_1P0#T37) U14.T39(VCCAREF_GBE_HVGEN#T39) U14.T44(VCCAPLL_SATA3_1P0#T44) U14.T45(VCCAPLL_SATA_1P0#T45) U14.V20(VCCADLLDDR_1_1P0#V20) U14.V21(VCCADLLDDR_1_1P0#V21) U14.V23(VCCADLLDDR_1_1P0#V23) U14.V25(VCCADLLDDR_1_1P0#V25) U14.V26(VCCADLLDDR_1_1P0#V26) U14.V38(VCCA_GBE_1P0#V38) U14.V39(VCCAREF_GBE_HVGEN#V39) U14.V41(VCCAPLL_GBE_1P0#V41) U14.V46(VCCAREF_SATA_HVGEN#V46) U14.W21(VCCADDR_1_1P0#W21) U14.W23(VCCADDR_1_1P0#W23) U14.W25(VCCADDR_1_1P0#W25) U14.W26(VCCADDR_1_1P0#W26) U14.W38(VCCA_GBE_1P0#W38) U14.W41(VCCAPLL_GBE_1P0#W41) U14.W44(VCCAREF_SATA_HVGEN#W44) U14.W46(VCCAREF_SATA_HVGEN#W46)
V1P0_LDOOUT: C165.1 U31.6(S_CTRL) U31.10(VCC/LDO_OUT)
V1P1: C113.2 C120.1 C121.1 C332.1 C341.1 C445.1 C452.2 L9.2 R327.1 U14.AD31(VCCRAMCPUSI1_1P03#AD31) U14.AD32(VCCRAMCPUSI1_1P03#AD32) U14.AF29(VCCRAMCPUSI1_1P03#AF29) U14.AF31(VCCRAMCPUSI1_1P03#AF31) U14.AG29(VCCRAMCPUSI1_1P03#AG29) U14.AG31(VCCRAMCPUSI1_1P03#AG31) U14.AG32(VCCRAMCPUSI1_1P03#AG32) U25.1(VO)
V1P1_FB: C478.1 R324.2 R325.2 R331.1 U25.2(VFB) U40.2(SOURCE)
V1P1_MARGIN_DN_D: R335.1 U40.3(DRAIN)
V1P1_MARGIN_DN_G: N54.2 U40.1(GATE)
V1P1_MARGIN_UP_D: R324.1 U39.3(DRAIN)
V1P1_MARGIN_UP_G: N53.2 U39.1(GATE)
V1P1_SS: C134.1 U25.4(SS)
V1P1_SW: C421.2 L9.1 U25.10(SW1) U25.11(SW2)
V1P1_VBST: C421.1 R302.2
V1P1_VREGS: C136.2 U25.3(VREG5)
V1P5: C143.1 L20.1 R125.2 U28.9(OUT1) U28.10(OUT2)
V1P5_CLK_LVIO: C471.1 C477.1 C482.1 L20.2 R326.1 R329.1 U27.30(VDDSRC_LVIO)
V1P5_CLK_VDD_CORE: C456.2 C475.1 R329.2 U27.21(VDD_CORE1_1P5) U27.40(VDD_CORE2_1P5)
V1P5_CLK_VDDIF: C454.1 C455.1 R326.2 U27.41(VDDIFF_CORE_1P5)
V1P8: C144.1 C295.1 C319.1 R334.2 U14.AF41(VCCPADXXXSUS_1P8#AF41) U14.AF42(VCCPADXXXSUS_1P8#AF42) U14.AJ41(VCCPADXXXSI0_1P8#AJ41) U14.AL41(VCCPADXXXSI0_1P8#AL41) U14.AU46(VCCUSBSUS_1P8#AU46) U14.AU47(VCCUSBSUS_1P8#AU47) U30.9(OUT1) U30.10(OUT2)
V1P8A: C18.1 C21.1 C224.1 C225.1 C229.1 C234.1 Q1.2(VOUT) R12.1 U7.F10(IO_2_F10/DIFFIO_T14N) U7.G11(IO_3_G11) U7.H8(VCCINT#H8) U7.H10(VCCINT#H10) U7.J7(VCCINT#J7) U7.J9(VCCINT#J9) U7.K6(IO_1_K6) U7.L7(IO_4_L7/DIFFIO_B9N)
V1P35: C128.1 C129.1 C133.1 C138.1 C378.1 C379.1 C426.1 C435.1 C438.1 C453.1 C463.1 C464.1 C470.1 R323.2 U14.AA32(VCCSFRXXXSI0_1P35#AA32) U14.AA34(VCCSFRXXXSI0_1P35#AA34) U14.AT31(VCCSFRPLLDDR_0_1P5) U14.V31(VCCSFRPLLDDR_1_1P5) U14.V34(VCCSFRXXXSI0_1P35#V34) U14.W34(VCCSFRXXXSI0_1P35#W34) U26.9(OUT1) U26.10(OUT2)
V3P3: C67.2 C79.2 C114.1 C115.1 C117.1 C130.2 C137.1 C153.2 C162.1 C163.1 C293.1 C299.1 C320.1 C338.2 C344.1 C346.1 C392.1 C394.1 C395.2 C436.1 C437.1 C442.1 C462.2 C465.1 C485.1 JP2.3 L6.1 L8.1 L10.2 L18.1 L21.1 R31.1 R37.2 R41.1 R43.1 R46.1 R47.1 R56.2 R57.1 R60.2 R62.1 R65.1 R78.2 R80.1 R81.1 R83.1 R84.1 R91.1 R92.1 R94.1 R95.1 R101.1 R102.1 R103.2 R112.1 R113.2 R115.2 R206.1 R210.1 R216.1 R217.1 R241.1 R243.2 R250.1 R268.1 R269.2 R270.1 R282.2 R288.1 R289.1 R293.1 R297.1 R301.1 R312.1 R313.2 R314.1 U14.AD42(VCCPADXXXSUS_3P3#AD42) U14.AD44(VCCPADXXXSUS_3P3#AD44) U14.AJ42(VCCPADXXXSI0_3P3) U14.AU42(VCCUSBSUS_3P3#AU42) U14.AW42(VCCUSBSUS_3P3#AW42) U22.2(A2) U24.8(VCC) U26.1(IN1) U26.2(IN2) U28.1(IN1) U28.2(IN2) U30.1(IN1) U30.2(IN2) U32.1(VDD) U33.5(VDD) U34.1(VDD) U35.5(VDD)
V3P3_CLK_PCI: C461.1 C468.1 R328.2 U27.7(VDDPCI_3V3)
V3P3_CLK_VDD25: C479.1 C480.1 C481.1 R330.2 U27.14(VDD25) U27.15(VDD48)
V3P3_CLK_XTAL: C459.1 C460.1 L18.2 U27.3(VDDREF)
V3P3_CLKBUF_VDD: C372.1 C387.1 C388.1 C404.1 C406.1 C407.1 C408.1 C409.1 C420.1 L8.2 R259.1 R266.1 U21.12(VDD1) U21.16(VDD2) U21.20(VDD3) U21.21(VDD4) U21.25(VDD5) U21.29(VDD6) U21.31(VDD7) U21.35(VDD8) U21.39(VDD9)
V3P3_CLKBUF_VDDA: C91.1 C360.1 R266.2 U21.1(VDDA)
V3P3_CLKBUF_VDDR: C361.1 C362.1 R259.2 U21.5(VDDR)
V3P3_SF100: JP5.3 U22.1(A1)
V3P3_SPI: C347.1 C358.1 R230.1 R232.1 R233.1 R235.1 R256.1 R260.1 U15.8(VCC) U16.8(VCC) U22.3(C)
V3P3A: C4.1 C5.1 C7.1 C8.1 C9.1 C11.1 C12.1 C17.1 C28.1 C55.1 C61.1 C81.1 C89.1 C123.1 C177.1 C179.1 C183.1 C185.1 C190.1 C194.1 C195.1 C202.1 C203.1 C206.1 C211.1 C213.1 C214.1 C217.1 C218.1 C222.1 C223.1 C228.1 C230.1 C236.1 C244.1 C245.1 C247.1 C249.1 C255.1 C258.1 C274.1 C277.1 C314.1 C331.1 C348.1 C399.1 C400.1 C405.1 C433.1 J1.1 J2.1 J3.1 J4.1 J5.1 JP3.4 L2.1 P1.199(VDDSPD) P4.199(VDDSPD) Q1.3(VIN) Q2.2(VOUT) R7.1 R16.1 R18.1 R40.1 R72.1 R74.1 R79.1 R118.1 R141.1 R145.1 R146.1 R148.2 R150.2 R151.2 R152.2 R153.2 R154.2 R156.2 R158.2 R159.1 R160.1 R161.1 R162.1 R163.1 R168.1 R169.1 R170.1 R171.1 R172.1 R175.2 R176.1 R187.1 R190.1 R191.2 R193.1 R194.1 R195.2 R199.1 R200.2 R203.1 R204.1 R205.1 R207.1 R208.2 R218.1 R244.2 R251.1 R252.1 R254.2 R267.2 R273.1 R337.1 R343.1 R350.2 R351.2 R356.1 U1.5(VCC) U3.28(VCC) U4.1(A1) U4.2(A2) U5.8(VDD) U6.1(VREFA) U7.A3(VCCIO2#A3) U7.A14(VCCIO2#A14) U7.C1(VCCIO1#C1) U7.C16(VCCIO3#C16) U7.F8(VCCIO2#F8) U7.F9(VCCIO2#F9) U7.H6(VCCIO1#H6) U7.H11(VCCIO3#H11) U7.J6(VCCIO1#J6) U7.J11(VCCIO3#J11) U7.L8(VCCIO4#L8) U7.L9(VCCIO4#L9) U7.P1(VCCIO1#P1) U7.P16(VCCIO3#P16) U7.T3(VCCIO4#T3) U7.T14(VCCIO4#T14) U8.8(VCC) U10.1(VREFA) U11.5(VCC) U13.5(VCC) U14.AG42(VCCRTC_3P3) U23.28(VCC) U36.5(VCC) U37.5(VCC) U38.10(VIN)
V5A: C24.1 C64.1 C67.1 C79.1 C82.1 C124.2 C126.2 C131.1 C132.1 C154.2 C164.2 C212.1 C220.2 C246.2 C338.1 C466.1 C467.1 C484.2 L4.1 L11.2 N12.1 Q2.3(VIN) R8.1 R54.1 R339.2 R354.1 U2.3(VCC) U2.20(BBRK_N) U12.3(VCC) U12.20(BBRK_N) U26.4(BIAS) U28.4(BIAS) U29.1(VO) U30.4(BIAS)
V12A: C1.1 C3.1 C15.1 C23.1 C38.1 C45.1 C50.1 C52.1 C54.1 C58.1 C59.1 C60.1 C62.1 C63.2 C68.1 C69.1 C75.1 C83.1 C84.1 C85.1 C86.2 C87.1 C90.1 C93.1 C113.1 C118.1 C119.1 C127.1 C140.1 C141.1 C142.1 C150.2 C151.1 C152.1 C157.1 C170.1 C175.1 C178.1 C187.1 C262.1 C278.1 C314.2 C325.1 C326.1 C339.1 C348.2 C433.2 C440.1 C441.1 C443.1 C452.1 C469.1 C472.1 L13.2 N14.1 R19.1 R36.1 R68.1 R114.2 R276.1 S1.A2(P12V#A2) S1.A3(P12V#A3) S1.A81(P12V#A81) S1.A82(P12V#A82) S1.B1(P12V#B1) S1.B2(P12V#B2) S1.B3(P12V#B3) U2.14(VIN1) U2.15(VIN2) U2.16(VIN3) U12.14(VIN1) U12.15(VIN2) U12.16(VIN3) U17.12(VIN_12) U17.13(VIN_13) U17.14(VIN_14) U17.15(VIN_15) U17.16(VIN_16) U17.17(VIN_17) U18.1(D1) U18.2(D2) U18.5(D3) U18.6(D4) U18.7(D) U25.13(VIN) U25.14(VCC)
V12A_PM_V1P0: C145.1 C146.1 C147.1 C148.2 C149.1 L13.1 U31.9(VIN) U31.13(PVIN)
VCC3P3_SATA1: C76.1 L6.2 P3.8 P3.9 P3.10
VCC5_SATA1: C42.1 C46.1 C51.1 C57.1 L4.2 P3.14 P3.15 P3.16
VCCA_PCIE_1P0: U14.AW38(VCCA_PCIE_1P0#AW38) U14.AW39(VCCA_PCIE_1P0#AW39)
VCCA_PLLDDR0_AVN: C233.1 L16.1 U14.AU31(VCCPLLDDR_0_1P0)
VCCA_PLLDDR1_AVN: C353.1 L12.1 U14.W31(VCCPLLDDR_1_1P0)
VCCACKDDR_0: C296.1 L17.2 U14.AT32(VCCACKDDR_0_1P0#AT32) U14.AU32(VCCACKDDR_0_1P0#AU32)
VCCACKDDR_1: C380.1 L3.2 U14.V28(VCCACKDDR_1_1P0#V28) U14.W28(VCCACKDDR_1_1P0#W28)
VCCCLKDDR0: C231.1 C232.1 C289.1 L15.2 U14.AT29(VCCCLKDDR_0_1P5#AT29) U14.AU29(VCCCLKDDR_0_1P5#AU29)
VCCCLKDDR1: C383.1 C446.1 C451.1 L19.2 U14.V29(VCCCLKDDR_1_1P5#V29) U14.W29(VCCCLKDDR_1_1P5#W29)
VCCP: C23.2 C38.2 C43.1 C44.1 C47.1 C48.1 C49.1 C73.1 C74.1 C75.2 C238.1 C239.1 C259.1 C265.1 C266.1 C267.1 C269.1 C270.1 C271.1 C272.1 C297.1 C298.1 C302.1 C309.1 C313.1 C317.1 C321.1 C322.1 C328.1 C334.1 C335.1 C336.1 C337.1 C340.1 C345.1 C351.1 L5.2 N37.1 R39.1 R246.1 U14.AD21(VCCCPUVIDSI0_1P03#AD21) U14.AD23(VCCCPUVIDSI0_1P03#AD23) U14.AD25(VCCCPUVIDSI0_1P03#AD25) U14.AD26(VCCCPUVIDSI0_1P03#AD26) U14.AE1(VCCCPUVIDSI0_1P03#AE1) U14.AE5(VCCCPUVIDSI0_1P03#AE5) U14.AF4(VCCCPUVIDSI0_1P03#AF4) U14.AF20(VCCCPUVIDSI0_1P03#AF20) U14.AF21(VCCCPUVIDSI0_1P03#AF21) U14.AF23(VCCCPUVIDSI0_1P03#AF23) U14.AF25(VCCCPUVIDSI0_1P03#AF25) U14.AF26(VCCCPUVIDSI0_1P03#AF26) U14.AG7(VCCCPUVIDSI0_1P03#AG7) U14.AG8(VCCCPUVIDSI0_1P03#AG8) U14.AG11(VCCCPUVIDSI0_1P03#AG11) U14.AG13(VCCCPUVIDSI0_1P03#AG13) U14.AG14(VCCCPUVIDSI0_1P03#AG14) U14.AG17(VCCCPUVIDSI0_1P03#AG17) U14.AG19(VCCCPUVIDSI0_1P03#AG19) U14.AG21(VCCCPUVIDSI0_1P03#AG21) U14.AH1(VCCCPUVIDSI0_1P03#AH1) U14.AH3(VCCCPUVIDSI0_1P03#AH3) U14.AH4(VCCCPUVIDSI0_1P03#AH4) U14.AH7(VCCCPUVIDSI0_1P03#AH7) U14.AH8(VCCCPUVIDSI0_1P03#AH8) U14.AH10(VCCCPUVIDSI0_1P03#AH10) U14.AH13(VCCCPUVIDSI0_1P03#AH13) U14.AH14(VCCCPUVIDSI0_1P03#AH14) U14.AH16(VCCCPUVIDSI0_1P03#AH16) U14.AH19(VCCCPUVIDSI0_1P03#AH19) U14.AJ2(VCCCPUVIDSI0_1P03#AJ2) U14.AJ4(VCCCPUVIDSI0_1P03#AJ4) U14.AJ5(VCCCPUVIDSI0_1P03#AJ5) U14.AJ21(VCCCPUVIDSI0_1P03#AJ21) U14.AJ23(VCCCPUVIDSI0_1P03#AJ23) U14.AJ25(VCCCPUVIDSI0_1P03#AJ25) U14.AJ26(VCCCPUVIDSI0_1P03#AJ26) U14.AK20(VCCCPUVIDSI0_1P03#AK20) U14.AL21(VCCCPUVIDSI0_1P03#AL21) U14.AL23(VCCCPUVIDSI0_1P03#AL23) U14.AL25(VCCCPUVIDSI0_1P03#AL25) U14.AL26(VCCCPUVIDSI0_1P03#AL26)
VCCP_RCSM: R59.2 R97.1 R98.2
VCCP_RCSP: R59.1 R98.1 R100.1
VCCP_TSEN_N: N13.1 R110.2
VCCP_TSEN_P: C102.1 R86.2 R110.1 U23.7(TSEN1)
VCCP_VR_HOT_N: R252.2 U3.16(VRHOT_ICRIT_N) U7.F3(IO_1_F3/DIFFIO_L4N) U23.16(VRHOT_ICRIT_N)
VDDQ_CPU_DDR: C22.1 C30.1 C56.1 C65.1 C72.1 C77.1 C88.1 C97.1 C99.1 C150.1 C164.1 C166.1 C167.1 C171.1 C172.1 C180.1 C181.1 C182.1 C186.1 C188.1 C189.1 C191.1 C192.1 C193.1 C196.1 C198.1 C215.1 C220.1 C221.1 C226.1 C237.1 C246.1 C248.1 C251.1 C252.1 C256.1 C261.1 C263.1 C268.1 C273.1 C275.1 C276.1 C279.1 C280.1 C281.1 C282.1 C283.1 C285.1 C291.1 C301.1 C311.1 C315.1 C324.1 C333.1 C355.1 C356.1 C366.1 C382.1 C385.1 C386.1 C391.1 C396.1 C398.1 C401.1 C402.1 C413.1 C415.1 C416.1 C417.1 C418.1 C422.1 C423.1 C424.1 C427.1 C432.1 C439.1 C457.1 C458.1 C474.1 L1.2 L15.1 L19.1 N27.1 N33.1 N34.1 P1.85(VDD1) P1.86(VDD8) P1.93(VDD2) P1.94(VDD9) P1.101(VDD3) P1.102(VDD10) P1.109(VDD4) P1.110(VDD11) P1.115(VDD5) P1.116(VDD12) P1.123(VDD6) P1.124(VDD13) P1.131(VDD7) P1.132(VDD14) P4.85(VDD1) P4.86(VDD8) P4.93(VDD2) P4.94(VDD9) P4.101(VDD3) P4.102(VDD10) P4.109(VDD4) P4.110(VDD11) P4.115(VDD5) P4.116(VDD12) P4.123(VDD6) P4.124(VDD13) P4.131(VDD7) P4.132(VDD14) R1.1 R5.1 R9.1 R131.1 R133.1 R136.1 R138.1 R139.1 R180.1 R182.1 R222.1 R239.1 R291.1 R292.1 R309.1 R319.1 U14.AY19(VCCDDR_0_1P5#AY19) U14.AY21(VCCDDR_0_1P5#AY21) U14.AY23(VCCDDR_0_1P5#AY23) U14.BC7(VCCDDR_0_1P5#BC7) U14.BC10(VCCDDR_0_1P5#BC10) U14.BC13(VCCDDR_0_1P5#BC13) U14.BC15(VCCDDR_0_1P5#BC15) U14.BD17(VCCDDR_0_1P5#BD17) U14.BD21(VCCDDR_0_1P5#BD21) U14.BD25(VCCDDR_0_1P5#BD25) U14.BE19(VCCDDR_0_1P5#BE19) U14.BE26(VCCDDR_0_1P5#BE26) U14.BF13(VCCDDR_0_1P5#BF13) U14.BF23(VCCDDR_0_1P5#BF23) U14.BG9(VCCDDR_0_1P5#BG9) U14.BG15(VCCDDR_0_1P5#BG15) U14.BH17(VCCDDR_0_1P5#BH17) U14.BJ4(VCCDDR_0_1P5#BJ4) U14.BK6(VCCDDR_0_1P5#BK6) U14.BK9(VCCDDR_0_1P5#BK9) U14.BK12(VCCDDR_0_1P5#BK12) U14.BK13(VCCDDR_0_1P5#BK13) U14.BL7(VCCDDR_0_1P5#BL7) U14.BM9(VCCDDR_0_1P5#BM9) U14.E7(VCCDDR_1_1P5#E7) U14.E9(VCCDDR_1_1P5#E9) U14.G5(VCCDDR_1_1P5#G5) U14.G7(VCCDDR_1_1P5#G7) U14.H13(VCCDDR_1_1P5#H13) U14.H14(VCCDDR_1_1P5#H14) U14.J5(VCCDDR_1_1P5#J5) U14.K10(VCCDDR_1_1P5#K10) U14.K17(VCCDDR_1_1P5#K17) U14.K18(VCCDDR_1_1P5#K18) U14.K25(VCCDDR_1_1P5#K25) U14.K26(VCCDDR_1_1P5#K26) U14.L5(VCCDDR_1_1P5#L5) U14.L21(VCCDDR_1_1P5#L21) U14.L22(VCCDDR_1_1P5#L22) U14.M3(VCCDDR_1_1P5#M3) U14.N13(VCCDDR_1_1P5#N13) U14.N14(VCCDDR_1_1P5#N14) U14.P17(VCCDDR_1_1P5#P17) U14.P18(VCCDDR_1_1P5#P18) U14.P25(VCCDDR_1_1P5#P25) U14.P26(VCCDDR_1_1P5#P26) U14.R21(VCCDDR_1_1P5#R21) U14.R22(VCCDDR_1_1P5#R22) U32.6(RH) U34.6(RH) U38.2(VLDOIN)
VDDQ_CPU_SEN_N: N2.1 N31.2 N32.2
VDDQ_CPU_SEN_P: N1.1 N33.2 N34.2
VDDQ_RCSM: R4.2 R6.1 R15.2
VDDQ_RCSP: R2.1 R4.1 R15.1
VDDQ_TSEN_N: N3.1 R17.2
VDDQ_TSEN_P: C19.1 R11.2 R17.1 U3.7(TSEN1)
7-SEGMENT CONTROL: J4.2 U7.L15(IO_3_L15/DIFFIO_R18P)
BIAS3P3: R122.1
C0_CLK: R257.2 U15.6(SCK)
C0_CS: R49.2 U15.1(CS#)
C0_MO: R258.2 U15.5(SI/IO0)
C1_CLK: R247.2 U16.6(SCK)
C1_CS: R229.2 U16.1(CS#)
C1_MO: R248.2 U16.5(SI/IO0)
CLK_14M_SOC: R120.1 U14.AM56(CLK14_IN)
CLK_25M_CPLD: R186.2 U7.H5(IO_1_H5/CLK0)
CLK_25M_CPLD_R: R186.1 X1.3(CLK)
CLK_96M_SOC_USB_DN: U14.BA50(USB_REFCLKN) U27.20(DOT96_N_LRS_SRC6_N_LRS)
CLK_96M_SOC_USB_DP: U14.BB50(USB_REFCLKP) U27.19(DOT96_LRS_SRC6_LRS)
CLK_100M_CLKBUFF_DN: U21.7(DIF_IN_N) U27.26(SRC5_N_LRS)
CLK_100M_CLKBUFF_DP: U21.6(DIF_IN) U27.27(SRC5_LRS)
CLK_100M_PCIE0_SLOT_DN: S1.A14(PCIE0_REFCLK_N) U21.18(DIF_1_N)
CLK_100M_PCIE0_SLOT_DP: S1.A13(PCIE0_REFCLK_P) U21.17(DIF_1)
CLK_100M_PCIE1_SLOT_DN: S1.B36(PCIE1_REFCLK_N) U21.24(DIF_2_N)
CLK_100M_PCIE1_SLOT_DP: S1.B35(PCIE1_REFCLK_P) U21.23(DIF_2)
CLK_100M_SOC_GBE_DN: U14.D50(GBE_REFCLKN) U27.45(DIF0_N_LRS)
CLK_100M_SOC_GBE_DP: U14.B50(GBE_REFCLKP) U27.46(DIF0_LRS)
CLK_100M_SOC_HFHPLL_DN: U14.J37(HPLL_REFN) U27.35(SRC2_N_LRS)
CLK_100M_SOC_HFHPLL_DP: U14.L37(HPLL_REFP) U27.36(SRC2_LRS)
CLK_100M_SOC_MPLL0_DN: U14.BM13(DDR3_0_REFN) U27.28(SRC4_N_LRS)
CLK_100M_SOC_MPLL0_DP: U14.BN12(DDR3_0_REFP) U27.29(SRC4_LRS)
CLK_100M_SOC_MPLL1_DN: U14.L14(DDR3_1_REFN) U27.32(SRC3_N_LRS)
CLK_100M_SOC_MPLL1_DP: U14.J14(DDR3_1_REFP) U27.33(SRC3_LRS)
CLK_100M_SOC_PCIE_DN: U14.BD49(PCIE_REFCLKN) U21.15(DIF_0_N)
CLK_100M_SOC_PCIE_DP: U14.BB49(PCIE_REFCLKP) U21.14(DIF_0)
CLK_100M_SOC_SATA3_DN: U14.L59(SATA3_REFCLKN) U27.23(SATA_N_LRS)
CLK_100M_SOC_SATA3_DP: U14.L57(SATA3_REFCLKP) U27.22(SATA_LRS)
CLK_100M_SOC_SATA_DN: U14.L54(SATA_REFCLKN) U21.37(DIF_5_N)
CLK_100M_SOC_SATA_DP: U14.J54(SATA_REFCLKP) U21.36(DIF_5)
CLK_100M_XDP_DN: P2.42(ITPCLK#/HOOK5) U27.38(SRC1_N_LRS)
CLK_100M_XDP_DP: P2.40(ITPCLK/HOOK4) U27.39(SRC1_LRS)
CLK_C: R117.1 U14.P50(GBE_SMBCLK)
CLK_LPC0: R28.1 U7.M4(IO_1_M4/DIFFIO_L20N)
CLK_LPC0_R: R28.2 U14.AG51(LPC_CLKOUT0)
CLK_LPC1: R26.1 TP3.1
CLK_LPC1_R: R26.2 U14.AM49(LPC_CLKOUT1)
CLKPWRGD: R318.1 U7.K3(IO_1_K3) U21.3(CLKPWRGD_PD_N) U27.47(CLKPWRGD_PD_N_3V3)
CPLD_AD1: J3.2 U7.T7(IO_4_T7/DIFFIO_B10N)
CPLD_AD2: J2.2 U7.T8(IO_4_T8/DIFFIO_B12N)
CPLD_AD3: J1.2 U7.T9(IO_4_T9/DIFFIO_B13P)
CPLD_TCK: JP3.1 R144.2 U7.P3(TCK)
CPLD_TDI: JP3.9 R159.2 U7.L6(TDI)
CPLD_TDO: JP3.3 R141.2 U7.M5(TDO)
CPLD_TMS: JP3.5 R176.2 U7.N4(TMS)
CPU_GBE_LED_0: R295.2 U14.P46(GBE_LED0)
CPU_GBE_LED_1: R278.2 U14.W50(GBE_LED1)
CPU_GBE_LED_2: R294.2 U14.P48(GBE_LED2)
CPU_GBE_LED_3: R271.2 U14.R58(GBE_LED3)
CPU_IERR_N: R243.1 U7.K16(IO_3_K16/DIFFIO_R15P) U14.AM52(I\E\R\R\)
CPU_MCERR_N: R37.1 U7.K15(IO_3_K15/DIFFIO_R16P) U14.AL52(M\C\E\R\R\)
CPU_NMI: R226.1 U7.C12(IO_2_C12/DIFFIO_T20N) U14.AL56(NMI)
CPU_PROCHOT_1P0_N: R220.1 U10.4(B1) U14.BB59(P\R\O\C\H\O\T\)
CPU_PROCHOT_3P3_N: R40.2 U7.C7(IO_2_C7/DIFFIO_T5N) U10.3(A1)
CPU_PROCHOT_DIR: R35.1 U7.C8(IO_2_C8/DIFFIO_T9P) U10.5(DIR)
CPU_PWRBTN_N: R297.2 U7.J2(IO_1_J2/DIFFIO_L12N) U14.AC49(P\M\U\_\P\W\R\B\T\N\)
CPU_RSTBTN_N: R210.2 U7.B8(IO_2_B8/DIFFIO_T10N) U14.AM58(P\M\U\_\R\E\S\E\T\B\U\T\T\O\N\)
CPU_RSVD_AR51: R51.2 U14.AR51(RSVD6)
CPU_RSVD_AR53: R197.1 R202.2 U14.AR53(RSVD7)
CPU_RSVD_AR54: R225.2 U14.AR54(RSVD8)
CPU_THERMTRIP_1P0_N: R50.1 U6.4(B1) U14.AT56(T\H\E\R\M\T\R\I\P\)
CPU_THERMTRIP_3P3_N: R190.2 U6.3(A1) U7.C5(IO_2_C5/DIFFIO_T2N)
CSN1_VCCP: C419.2 N37.2 R290.2
CSN1_VCCP_R: R290.1 U23.40(IRTN_1)
CSN1_VDDQ_CH01: C184.2 N27.2 R143.2
CSN1_VNN: C444.2 N43.2 R108.2 R316.2
CSN1_VNN_R: R108.1 U23.32(IRTN_1_L2)
CSP1_VCCP: N38.2 R287.2
CSP1_VCCP_R: R284.1 U23.39(ISEN_1)
CSP1_VDDQ_CH01: N28.2 R142.2
CSP1_VNN: N44.2 R320.2
CSP1_VNN_R: R107.1 U23.31(ISEN_1_L2)
CTBTRIGINOUT: R224.1 U14.AM47(CTBTRIGINOUT)
CTBTRIGOUT: R185.1 U14.AL47(CTBTRIGOUT)
DAT_C: R67.1 U14.T59(GBE_SMBD)
DDR3_0_DRAM_PWROK: C173.1 R139.2 U14.BG17(DDR3_0_DRAM_PWROK) U36.4(OUT)
DDR3_0_VCCA_PWROK: C241.1 R9.2 U1.4(OUT) U14.BE17(DDR3_0_VCCA_PWROK)
DDR3_1_DRAM_PWROK: C300.1 R222.2 U11.4(OUT) U14.L17(DDR3_1_DRAM_PWROK)
DDR3_1_VCCA_PWROK: C390.1 R239.2 U13.4(OUT) U14.N17(DDR3_1_VCCA_PWROK)
DDR3_CPU_CH0_BA0: P1.119(BA0) U14.BL12(DDR3_0_BS_0)
DDR3_CPU_CH0_BA1: P1.108(BA1) U14.BL10(DDR3_0_BS_1)
DDR3_CPU_CH0_BA2: P1.91(BA2) U14.BC8(DDR3_0_BS_2)
DDR3_CPU_CH0_CAS_N: P1.125(CAS#) U14.BH26(D\D\R\3\_\0\_\C\A\S\)
DDR3_CPU_CH0_CK_DN0: P1.113(CK0#) U14.BC21(D\D\R\3\_\0\_\C\K\0\)
DDR3_CPU_CH0_CK_DN1: P1.114(CK1#) U14.BG21(D\D\R\3\_\0\_\C\K\1\)
DDR3_CPU_CH0_CK_DP0: P1.111(CK0) U14.BA21(DDR3_0_CK_0)
DDR3_CPU_CH0_CK_DP1: P1.112(CK1) U14.BF21(DDR3_0_CK_1)
DDR3_CPU_CH0_CKE0: P1.87(CKE0) U14.BG4(DDR3_0_CKE_0)
DDR3_CPU_CH0_CKE1: P1.89(CKE1) U14.BH5(DDR3_0_CKE_1)
DDR3_CPU_CH0_CS_N0: P1.127(CS0#) U14.BE25(D\D\R\3\_\0\_\C\S\0\)
DDR3_CPU_CH0_CS_N1: P1.129(NC/CS1#) U14.BB25(D\D\R\3\_\0\_\C\S\1\)
DDR3_CPU_CH0_DQ0: P1.5(DQ0) U14.AM15(DDR3_0_DQ_0)
DDR3_CPU_CH0_DQ1: P1.7(DQ1) U14.AM14(DDR3_0_DQ_1)
DDR3_CPU_CH0_DQ2: P1.13(DQ2) U14.AL8(DDR3_0_DQ_2)
DDR3_CPU_CH0_DQ3: P1.15(DQ3) U14.AM8(DDR3_0_DQ_3)
DDR3_CPU_CH0_DQ4: P1.4(DQ4) U14.AM17(DDR3_0_DQ_4)
DDR3_CPU_CH0_DQ5: P1.6(DQ5) U14.AL15(DDR3_0_DQ_5)
DDR3_CPU_CH0_DQ6: P1.16(DQ6) U14.AM11(DDR3_0_DQ_6)
DDR3_CPU_CH0_DQ7: P1.18(DQ7) U14.AM9(DDR3_0_DQ_7)
DDR3_CPU_CH0_DQ8: P1.19(DQ8) U14.AR14(DDR3_0_DQ_8)
DDR3_CPU_CH0_DQ9: P1.21(DQ9) U14.AT13(DDR3_0_DQ_9)
DDR3_CPU_CH0_DQ10: P1.31(DQ10) U14.AT10(DDR3_0_DQ_10)
DDR3_CPU_CH0_DQ11: P1.33(DQ11) U14.AR11(DDR3_0_DQ_11)
DDR3_CPU_CH0_DQ12: P1.22(DQ12) U14.AR16(DDR3_0_DQ_12)
DDR3_CPU_CH0_DQ13: P1.24(DQ13) U14.AT14(DDR3_0_DQ_13)
DDR3_CPU_CH0_DQ14: P1.34(DQ14) U14.AT8(DDR3_0_DQ_14)
DDR3_CPU_CH0_DQ15: P1.36(DQ15) U14.AR10(DDR3_0_DQ_15)
DDR3_CPU_CH0_DQ16: P1.37(DQ16) U14.AY9(DDR3_0_DQ_16)
DDR3_CPU_CH0_DQ17: P1.39(DQ17) U14.AY11(DDR3_0_DQ_17)
DDR3_CPU_CH0_DQ18: P1.49(DQ18) U14.AY15(DDR3_0_DQ_18)
DDR3_CPU_CH0_DQ19: P1.51(DQ19) U14.AW17(DDR3_0_DQ_19)
DDR3_CPU_CH0_DQ20: P1.40(DQ20) U14.AW8(DDR3_0_DQ_20)
DDR3_CPU_CH0_DQ21: P1.42(DQ21) U14.AY8(DDR3_0_DQ_21)
DDR3_CPU_CH0_DQ22: P1.48(DQ22) U14.AY14(DDR3_0_DQ_22)
DDR3_CPU_CH0_DQ23: P1.50(DQ23) U14.AW15(DDR3_0_DQ_23)
DDR3_CPU_CH0_DQ24: P1.55(DQ24) U14.AN4(DDR3_0_DQ_24)
DDR3_CPU_CH0_DQ25: P1.57(DQ25) U14.AN2(DDR3_0_DQ_25)
DDR3_CPU_CH0_DQ26: P1.63(DQ26) U14.AU1(DDR3_0_DQ_26)
DDR3_CPU_CH0_DQ27: P1.65(DQ27) U14.AU3(DDR3_0_DQ_27)
DDR3_CPU_CH0_DQ28: P1.54(DQ28) U14.AL2(DDR3_0_DQ_28)
DDR3_CPU_CH0_DQ29: P1.56(DQ29) U14.AL4(DDR3_0_DQ_29)
DDR3_CPU_CH0_DQ30: P1.66(DQ30) U14.AR2(DDR3_0_DQ_30)
DDR3_CPU_CH0_DQ31: P1.68(DQ31) U14.AR4(DDR3_0_DQ_31)
DDR3_CPU_CH0_DQ32: P1.133(DQ32) U14.BA32(DDR3_0_DQ_32)
DDR3_CPU_CH0_DQ33: P1.135(DQ33) U14.BA30(DDR3_0_DQ_33)
DDR3_CPU_CH0_DQ34: P1.145(DQ34) U14.BF30(DDR3_0_DQ_34)
DDR3_CPU_CH0_DQ35: P1.147(DQ35) U14.BD30(DDR3_0_DQ_35)
DDR3_CPU_CH0_DQ36: P1.134(DQ36) U14.BB32(DDR3_0_DQ_36)
DDR3_CPU_CH0_DQ37: P1.136(DQ37) U14.AY30(DDR3_0_DQ_37)
DDR3_CPU_CH0_DQ38: P1.142(DQ38) U14.BG29(DDR3_0_DQ_38)
DDR3_CPU_CH0_DQ39: P1.144(DQ39) U14.BG30(DDR3_0_DQ_39)
DDR3_CPU_CH0_DQ40: P1.151(DQ40) U14.BL16(DDR3_0_DQ_40)
DDR3_CPU_CH0_DQ41: P1.153(DQ41) U14.BL17(DDR3_0_DQ_41)
DDR3_CPU_CH0_DQ42: P1.159(DQ42) U14.BL21(DDR3_0_DQ_42)
DDR3_CPU_CH0_DQ43: P1.161(DQ43) U14.BN21(DDR3_0_DQ_43)
DDR3_CPU_CH0_DQ44: P1.148(DQ44) U14.BM16(DDR3_0_DQ_44)
DDR3_CPU_CH0_DQ45: P1.150(DQ45) U14.BP16(DDR3_0_DQ_45)
DDR3_CPU_CH0_DQ46: P1.160(DQ46) U14.BP19(DDR3_0_DQ_46)
DDR3_CPU_CH0_DQ47: P1.162(DQ47) U14.BN19(DDR3_0_DQ_47)
DDR3_CPU_CH0_DQ48: P1.165(DQ48) U14.BM25(DDR3_0_DQ_48)
DDR3_CPU_CH0_DQ49: P1.167(DQ49) U14.BP25(DDR3_0_DQ_49)
DDR3_CPU_CH0_DQ50: P1.177(DQ50) U14.BL28(DDR3_0_DQ_50)
DDR3_CPU_CH0_DQ51: P1.179(DQ51) U14.BN28(DDR3_0_DQ_51)
DDR3_CPU_CH0_DQ52: P1.166(DQ52) U14.BL23(DDR3_0_DQ_52)
DDR3_CPU_CH0_DQ53: P1.168(DQ53) U14.BN23(DDR3_0_DQ_53)
DDR3_CPU_CH0_DQ54: P1.174(DQ54) U14.BM27(DDR3_0_DQ_54)
DDR3_CPU_CH0_DQ55: P1.176(DQ55) U14.BP28(DDR3_0_DQ_55)
DDR3_CPU_CH0_DQ56: P1.183(DQ56) U14.BN32(DDR3_0_DQ_56)
DDR3_CPU_CH0_DQ57: P1.185(DQ57) U14.BK32(DDR3_0_DQ_57)
DDR3_CPU_CH0_DQ58: P1.191(DQ58) U14.BN35(DDR3_0_DQ_58)
DDR3_CPU_CH0_DQ59: P1.193(DQ59) U14.BM36(DDR3_0_DQ_59)
DDR3_CPU_CH0_DQ60: P1.180(DQ60) U14.BM31(DDR3_0_DQ_60)
DDR3_CPU_CH0_DQ61: P1.182(DQ61) U14.BL32(DDR3_0_DQ_61)
DDR3_CPU_CH0_DQ62: P1.192(DQ62) U14.BK35(DDR3_0_DQ_62)
DDR3_CPU_CH0_DQ63: P1.194(DQ63) U14.BL35(DDR3_0_DQ_63)
DDR3_CPU_CH0_DQS_DN0: P1.10(DQS0#) U14.AL12(D\D\R\3\_\0\_\D\Q\S\0\)
DDR3_CPU_CH0_DQS_DN1: P1.25(DQS1#) U14.AR7(D\D\R\3\_\0\_\D\Q\S\1\)
DDR3_CPU_CH0_DQS_DN2: P1.43(DQS2#) U14.AW11(D\D\R\3\_\0\_\D\Q\S\2\)
DDR3_CPU_CH0_DQS_DN3: P1.60(DQS3#) U14.AP1(D\D\R\3\_\0\_\D\Q\S\3\)
DDR3_CPU_CH0_DQS_DN4: P1.139(DQS4#) U14.BC29(D\D\R\3\_\0\_\D\Q\S\4\)
DDR3_CPU_CH0_DQS_DN5: P1.154(DQS5#) U14.BN17(D\D\R\3\_\0\_\D\Q\S\5\)
DDR3_CPU_CH0_DQS_DN6: P1.171(DQS6#) U14.BL26(D\D\R\3\_\0\_\D\Q\S\6\)
DDR3_CPU_CH0_DQS_DN7: P1.186(DQS7#) U14.BM34(D\D\R\3\_\0\_\D\Q\S\7\)
DDR3_CPU_CH0_DQS_DN8: P1.75(DQS8#) U14.BB4(DDR3_0_DQSBECC_0)
DDR3_CPU_CH0_DQS_DP0: P1.12(DQS0) U14.AL11(DDR3_0_DQS_0)
DDR3_CPU_CH0_DQS_DP1: P1.27(DQS1) U14.AT7(DDR3_0_DQS_1)
DDR3_CPU_CH0_DQS_DP2: P1.45(DQS2) U14.AW12(DDR3_0_DQS_2)
DDR3_CPU_CH0_DQS_DP3: P1.62(DQS3) U14.AP3(DDR3_0_DQS_3)
DDR3_CPU_CH0_DQS_DP4: P1.141(DQS4) U14.BD29(DDR3_0_DQS_4)
DDR3_CPU_CH0_DQS_DP5: P1.156(DQS5) U14.BM18(DDR3_0_DQS_5)
DDR3_CPU_CH0_DQS_DP6: P1.173(DQS6) U14.BN26(DDR3_0_DQS_6)
DDR3_CPU_CH0_DQS_DP7: P1.188(DQS7) U14.BP34(DDR3_0_DQS_7)
DDR3_CPU_CH0_DQS_DP8: P1.77(DQS8) U14.BB2(DDR3_0_DQSECC_0)
DDR3_CPU_CH0_ECC0: P1.69(CB0) U14.AY4(DDR3_0_DQECC_0)
DDR3_CPU_CH0_ECC1: P1.71(CB1) U14.AY2(DDR3_0_DQECC_1)
DDR3_CPU_CH0_ECC2: P1.81(CB2) U14.BD2(DDR3_0_DQECC_2)
DDR3_CPU_CH0_ECC3: P1.83(CB3) U14.BD4(DDR3_0_DQECC_3)
DDR3_CPU_CH0_ECC4: P1.72(CB4) U14.AW3(DDR3_0_DQECC_4)
DDR3_CPU_CH0_ECC5: P1.74(CB5) U14.AY1(DDR3_0_DQECC_5)
DDR3_CPU_CH0_ECC6: P1.80(CB6) U14.BC1(DDR3_0_DQECC_6)
DDR3_CPU_CH0_ECC7: P1.82(CB7) U14.BC3(DDR3_0_DQECC_7)
DDR3_CPU_CH0_MA0: P1.107(A0) U14.BH11(DDR3_0_MA_0)
DDR3_CPU_CH0_MA1: P1.105(A1) U14.BL8(DDR3_0_MA_1)
DDR3_CPU_CH0_MA2: P1.106(A2) U14.BG13(DDR3_0_MA_2)
DDR3_CPU_CH0_MA3: P1.103(A3) U14.BG11(DDR3_0_MA_3)
DDR3_CPU_CH0_MA4: P1.104(A4) U14.BD13(DDR3_0_MA_4)
DDR3_CPU_CH0_MA5: P1.99(A5) U14.BM7(DDR3_0_MA_5)
DDR3_CPU_CH0_MA6: P1.100(A6) U14.BD10(DDR3_0_MA_6)
DDR3_CPU_CH0_MA7: P1.98(A7) U14.BH8(DDR3_0_MA_7)
DDR3_CPU_CH0_MA8: P1.97(A8) U14.BD8(DDR3_0_MA_8)
DDR3_CPU_CH0_MA9: P1.92(A9) U14.BD15(DDR3_0_MA_9)
DDR3_CPU_CH0_MA10: P1.117(A10/AP) U14.BN10(DDR3_0_MA_10)
DDR3_CPU_CH0_MA11: P1.96(A11) U14.BG8(DDR3_0_MA_11)
DDR3_CPU_CH0_MA12: P1.95(A12) U14.BD7(DDR3_0_MA_12)
DDR3_CPU_CH0_MA13: P1.130(A13) U14.BA23(DDR3_0_MA_13)
DDR3_CPU_CH0_MA14: P1.90(A14) U14.BC11(DDR3_0_MA_14)
DDR3_CPU_CH0_MA15: P1.88(A15) U14.BF15(DDR3_0_MA_15)
DDR3_CPU_CH0_ODT0: P1.126(ODT0) U14.BD26(DDR3_0_ODT_0)
DDR3_CPU_CH0_ODT1: P1.128(NC/ODT1) U14.BB26(DDR3_0_ODT_1)
DDR3_CPU_CH0_RAS_N: P1.122(RAS#) U14.BG23(D\D\R\3\_\0\_\R\A\S\)
DDR3_CPU_CH0_RESET_N: N30.2 P1.30(RESET#) R180.2
DDR3_CPU_CH0_RESET_R_N: N30.1 R181.1 U14.BA25(D\D\R\3\_\0\_\D\R\A\M\R\S\T\)
DDR3_CPU_CH0_VREF: C227.1 R182.2 R189.1 U14.AY29(DDR3_0_VREF)
DDR3_CPU_CH0_VREFCA: C434.1 P1.84(VREFCA) R299.1 R309.2
DDR3_CPU_CH0_VREFDQ: N26.2 P1.1(VREFDQ)
DDR3_CPU_CH0_WE_N: P1.121(WE#) U14.BC23(D\D\R\3\_\0\_\W\E\)
DDR3_CPU_CH1_BA0: P4.119(BA0) U14.N18(DDR3_1_BS_0)
DDR3_CPU_CH1_BA1: P4.108(BA1) U14.H18(DDR3_1_BS_1)
DDR3_CPU_CH1_BA2: P4.91(BA2) U14.H25(DDR3_1_BS_2)
DDR3_CPU_CH1_CAS_N: P4.125(CAS#) U14.H4(D\D\R\3\_\1\_\C\A\S\)
DDR3_CPU_CH1_CK_DN0: P4.113(CK0#) U14.D8(D\D\R\3\_\1\_\C\K\0\)
DDR3_CPU_CH1_CK_DN1: P4.114(CK1#) U14.H9(D\D\R\3\_\1\_\C\K\1\)
DDR3_CPU_CH1_CK_DP0: P4.111(CK0) U14.C9(DDR3_1_CK_0)
DDR3_CPU_CH1_CK_DP1: P4.112(CK1) U14.G9(DDR3_1_CK_1)
DDR3_CPU_CH1_CKE0: P4.87(CKE0) U14.N26(DDR3_1_CKE_0)
DDR3_CPU_CH1_CKE1: P4.89(CKE1) U14.N25(DDR3_1_CKE_1)
DDR3_CPU_CH1_CS_N0: P4.127(CS0#) U14.K3(D\D\R\3\_\1\_\C\S\0\)
DDR3_CPU_CH1_CS_N1: P4.129(NC/CS1#) U14.N4(D\D\R\3\_\1\_\C\S\1\)
DDR3_CPU_CH1_DQ0: P4.5(DQ0) U14.B39(DDR3_1_DQ_0)
DDR3_CPU_CH1_DQ1: P4.7(DQ1) U14.D39(DDR3_1_DQ_1)
DDR3_CPU_CH1_DQ2: P4.13(DQ2) U14.B35(DDR3_1_DQ_2)
DDR3_CPU_CH1_DQ3: P4.15(DQ3) U14.D35(DDR3_1_DQ_3)
DDR3_CPU_CH1_DQ4: P4.4(DQ4) U14.A39(DDR3_1_DQ_4)
DDR3_CPU_CH1_DQ5: P4.6(DQ5) U14.C40(DDR3_1_DQ_5)
DDR3_CPU_CH1_DQ6: P4.16(DQ6) U14.A36(DDR3_1_DQ_6)
DDR3_CPU_CH1_DQ7: P4.18(DQ7) U14.C36(DDR3_1_DQ_7)
DDR3_CPU_CH1_DQ8: P4.19(DQ8) U14.B32(DDR3_1_DQ_8)
DDR3_CPU_CH1_DQ9: P4.21(DQ9) U14.C31(DDR3_1_DQ_9)
DDR3_CPU_CH1_DQ10: P4.31(DQ10) U14.A27(DDR3_1_DQ_10)
DDR3_CPU_CH1_DQ11: P4.33(DQ11) U14.C27(DDR3_1_DQ_11)
DDR3_CPU_CH1_DQ12: P4.22(DQ12) U14.E32(DDR3_1_DQ_12)
DDR3_CPU_CH1_DQ13: P4.24(DQ13) U14.D32(DDR3_1_DQ_13)
DDR3_CPU_CH1_DQ14: P4.34(DQ14) U14.D28(DDR3_1_DQ_14)
DDR3_CPU_CH1_DQ15: P4.36(DQ15) U14.B28(DDR3_1_DQ_15)
DDR3_CPU_CH1_DQ16: P4.37(DQ16) U14.D23(DDR3_1_DQ_16)
DDR3_CPU_CH1_DQ17: P4.39(DQ17) U14.B23(DDR3_1_DQ_17)
DDR3_CPU_CH1_DQ18: P4.49(DQ18) U14.D19(DDR3_1_DQ_18)
DDR3_CPU_CH1_DQ19: P4.51(DQ19) U14.B19(DDR3_1_DQ_19)
DDR3_CPU_CH1_DQ20: P4.40(DQ20) U14.C24(DDR3_1_DQ_20)
DDR3_CPU_CH1_DQ21: P4.42(DQ21) U14.D24(DDR3_1_DQ_21)
DDR3_CPU_CH1_DQ22: P4.48(DQ22) U14.B21(DDR3_1_DQ_22)
DDR3_CPU_CH1_DQ23: P4.50(DQ23) U14.D21(DDR3_1_DQ_23)
DDR3_CPU_CH1_DQ24: P4.55(DQ24) U14.H30(DDR3_1_DQ_24)
DDR3_CPU_CH1_DQ25: P4.57(DQ25) U14.H29(DDR3_1_DQ_25)
DDR3_CPU_CH1_DQ26: P4.63(DQ26) U14.N32(DDR3_1_DQ_26)
DDR3_CPU_CH1_DQ27: P4.65(DQ27) U14.L32(DDR3_1_DQ_27)
DDR3_CPU_CH1_DQ28: P4.54(DQ28) U14.H32(DDR3_1_DQ_28)
DDR3_CPU_CH1_DQ29: P4.56(DQ29) U14.J30(DDR3_1_DQ_29)
DDR3_CPU_CH1_DQ30: P4.66(DQ30) U14.M30(DDR3_1_DQ_30)
DDR3_CPU_CH1_DQ31: P4.68(DQ31) U14.P30(DDR3_1_DQ_31)
DDR3_CPU_CH1_DQ32: P4.133(DQ32) U14.R15(DDR3_1_DQ_32)
DDR3_CPU_CH1_DQ33: P4.135(DQ33) U14.R14(DDR3_1_DQ_33)
DDR3_CPU_CH1_DQ34: P4.145(DQ34) U14.R9(DDR3_1_DQ_34)
DDR3_CPU_CH1_DQ35: P4.147(DQ35) U14.R11(DDR3_1_DQ_35)
DDR3_CPU_CH1_DQ36: P4.134(DQ36) U14.T17(DDR3_1_DQ_36)
DDR3_CPU_CH1_DQ37: P4.136(DQ37) U14.U15(DDR3_1_DQ_37)
DDR3_CPU_CH1_DQ38: P4.142(DQ38) U14.R8(DDR3_1_DQ_38)
DDR3_CPU_CH1_DQ39: P4.144(DQ39) U14.U8(DDR3_1_DQ_39)
DDR3_CPU_CH1_DQ40: P4.151(DQ40) U14.U4(DDR3_1_DQ_40)
DDR3_CPU_CH1_DQ41: P4.153(DQ41) U14.U2(DDR3_1_DQ_41)
DDR3_CPU_CH1_DQ42: P4.159(DQ42) U14.AB2(DDR3_1_DQ_42)
DDR3_CPU_CH1_DQ43: P4.161(DQ43) U14.AB4(DDR3_1_DQ_43)
DDR3_CPU_CH1_DQ44: P4.148(DQ44) U14.T3(DDR3_1_DQ_44)
